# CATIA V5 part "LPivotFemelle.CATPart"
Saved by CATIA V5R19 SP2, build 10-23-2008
Part number: PivotFemelle
Publications: "Centre", "Axe", "Facteur d'échelle"
Bounding box of the stored display mesh (mm): x -5 to 5, y -4.99 to 4.99, z -10 to 10
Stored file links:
  E:\Mes documents\03_Ressources pédagogiques\01_Catia\Buggy Dassault\SchemaCinematiqueFinal\LPivotFemelle.CATPart
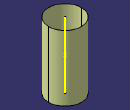
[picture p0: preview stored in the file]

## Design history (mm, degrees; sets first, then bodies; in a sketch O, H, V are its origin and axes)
External parameters (linked from other documents)
  `External.Facteur d'échelle` = 2
AxisSystem1: origin (0, 0, 0), X (1, 0, 0), Y (0, 1, 0), Z (0, 0, 1)
Body1 "PivotFemelle" (main body)
  Circle1: type CtrRad, Start 0, End 180, Center {point type Coord, X 0, Y 0, Z 0, RefAxis AxisSystem1}, Support xy-plane, Radius 5 {= 2.5mm*`External.Facteur d'échelle`}, FirstDirection (1, 0, 0)
  Extrude1: Element1 Circle1, Lim1 10 {= 5mm*`External.Facteur d'échelle`}, Lim2 10 {= 5mm*`External.Facteur d'échelle`}, Direction xy-plane
  Line1 "Axe": type PtPt, FirstPoint {point type Center, Curve edge of Extrude1}, SecondPoint {point type Center, Curve edge of Extrude1}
